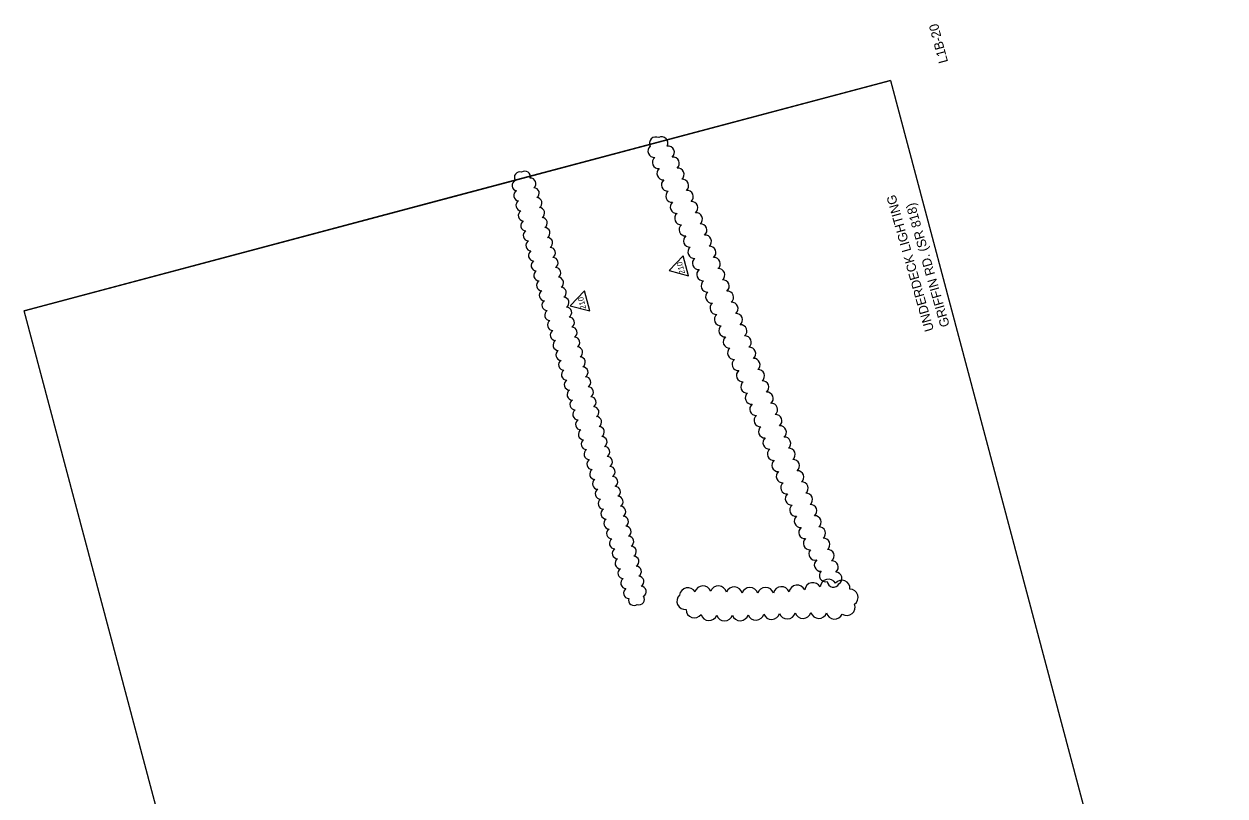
# Model space of a CAD drawing. Extents: x 930425 to 930963, y 629099 to 629760.
# Drawn here: x 930425 to 930939, y 629430 to 629760 of the extents above; entities that cross this region are included whole.
import ezdxf

# ---------------------------------------------------------------- set-up
doc = ezdxf.new("R2010")
doc.units = 0
for name, color, linetype in [('ActivePointCell_dp', 7, 'Continuous'), ('Cloud_dp', 7, 'Continuous'), ('MatchLines_dp', 7, 'Continuous'), ('TextShtNo', 7, 'Continuous'), ('TextTitle', 7, 'Continuous')]:
    doc.layers.add(name, color=color, linetype=linetype)

msp = doc.modelspace()

# ---------------------------------------------------------------- linework, layer by layer
at = {"layer": 'ActivePointCell_dp'}
msp.add_lwpolyline([(930567.78, 629098.98), (930424.61, 629637.39), (930795.69, 629736.06), (930938.85, 629197.65)], close=True, dxfattribs=at)
at = {"layer": 'Cloud_dp'}
for points in [[(930700.81, 629654.61), (930709.19, 629652.38), (930706.92, 629660.91)], [(930658.48, 629639.55), (930666.86, 629637.32), (930664.59, 629645.85)]]:
    msp.add_lwpolyline(points, close=True, dxfattribs=at)
for centre, radius, start, end in [((930695.16, 629709.11), 2.71, 63.2477, 208.2477), ((930697.65, 629709.14), 2.71, 332.9109, 117.9109), ((930694.48, 629705.73), 2.71, 128.986, 273.986), ((930700.39, 629705.22), 2.71, 312.0705, 97.0705), ((930696.39, 629700.94), 2.71, 129.4753, 274.4753), ((930702.48, 629700.51), 2.71, 310.9346, 95.9346), ((930704.51, 629695.77), 2.71, 310.3984, 95.3984), ((930636.89, 629694.51), 2.32, 70.1007, 215.1007), ((930639.1, 629694.86), 2.32, 342.9868, 127.9868), ((930641.48, 629691.87), 2.32, 309.1006, 94.1006), ((930698.31, 629696.14), 2.71, 129.2582, 274.2582), ((930700.22, 629691.34), 2.71, 129.1646, 274.1646), ((930706.5, 629691.02), 2.71, 310.0685, 95.0685), ((930635.93, 629691.06), 2.32, 113.8986, 258.8986), ((930636.61, 629686.76), 2.32, 119.116, 264.116), ((930642.9, 629687.76), 2.32, 303.8554, 88.8554), ((930702.13, 629686.54), 2.71, 129.1089, 274.1089), ((930708.48, 629686.25), 2.71, 309.8392, 94.8392), ((930637.55, 629682.46), 2.32, 120.4334, 265.4334), ((930644.08, 629683.52), 2.32, 302.3905, 87.3905), ((930704.03, 629681.74), 2.71, 129.0708, 274.0708), ((930710.43, 629681.47), 2.71, 309.6678, 94.6678), ((930638.56, 629678.17), 2.32, 121.1297, 266.1297), ((930645.22, 629679.25), 2.32, 302.3905, 87.3905), ((930705.92, 629676.94), 2.71, 129.0426, 274.0426), ((930712.37, 629676.69), 2.71, 309.5333, 94.5333), ((930639.62, 629673.88), 2.32, 121.5785, 266.5785), ((930646.35, 629674.98), 2.32, 302.3905, 87.3905), ((930647.5, 629670.71), 2.32, 302.5819, 87.5819), ((930707.82, 629672.13), 2.71, 129.0207, 274.0207), ((930714.3, 629671.9), 2.71, 309.4243, 94.4243), ((930640.7, 629669.6), 2.32, 121.8989, 266.8989), ((930648.65, 629666.44), 2.32, 302.7763, 87.7763), ((930709.71, 629667.33), 2.71, 129.003, 274.003), ((930716.23, 629667.11), 2.71, 309.3335, 94.3335), ((930641.81, 629665.33), 2.32, 122.1424, 267.1424), ((930642.93, 629661.06), 2.32, 122.3356, 267.3356), ((930649.82, 629662.18), 2.32, 302.7763, 87.7763), ((930711.61, 629662.52), 2.71, 128.9883, 273.9883), ((930718.15, 629662.32), 2.71, 309.2564, 94.2564), ((930644.07, 629656.79), 2.32, 122.4938, 267.4938), ((930650.98, 629657.92), 2.32, 302.7763, 87.7763), ((930713.5, 629657.72), 2.71, 128.9759, 273.9759), ((930720.06, 629657.52), 2.71, 309.1898, 94.1898), ((930645.22, 629652.53), 2.32, 122.6263, 267.6263), ((930652.15, 629653.66), 2.32, 302.7763, 87.7763), ((930715.39, 629652.91), 2.71, 128.9652, 273.9652), ((930721.96, 629652.72), 2.71, 309.1315, 94.1315), ((930646.37, 629648.27), 2.32, 122.7395, 267.7395), ((930653.31, 629649.4), 2.32, 302.7763, 87.7763), ((930654.47, 629645.13), 2.32, 302.7763, 87.7763), ((930717.28, 629648.11), 2.71, 128.9558, 273.9558), ((930723.86, 629647.92), 2.71, 309.08, 94.08), ((930647.54, 629644.01), 2.32, 122.8377, 267.8377), ((930655.64, 629640.87), 2.32, 302.7763, 87.7763), ((930719.16, 629643.3), 2.71, 128.9476, 273.9476), ((930725.76, 629643.12), 2.71, 309.0341, 94.0341), ((930648.71, 629639.75), 2.32, 122.9238, 267.9238), ((930649.89, 629635.49), 2.32, 123.0002, 268.0002), ((930656.8, 629636.61), 2.32, 302.7763, 87.7763), ((930721.05, 629638.49), 2.71, 128.9403, 273.9403), ((930727.65, 629638.32), 2.71, 308.9927, 93.9927), ((930651.07, 629631.23), 2.32, 123.0686, 268.0686), ((930657.97, 629632.35), 2.32, 302.7763, 87.7763), ((930722.94, 629633.69), 2.71, 128.9337, 273.9337), ((930729.54, 629633.51), 2.71, 308.9552, 93.9552), ((930652.26, 629626.98), 2.32, 123.1303, 268.1303), ((930659.13, 629628.09), 2.32, 302.7763, 87.7763), ((930724.83, 629628.88), 2.71, 128.9277, 273.9277), ((930731.43, 629628.71), 2.71, 308.921, 93.921), ((930733.31, 629623.9), 2.71, 308.8897, 93.8897), ((930653.45, 629622.73), 2.32, 123.1863, 268.1863), ((930660.29, 629623.82), 2.32, 302.7763, 87.7763), ((930661.46, 629619.56), 2.32, 302.7763, 87.7763), ((930726.71, 629624.07), 2.71, 128.9222, 273.9222), ((930728.6, 629619.27), 2.71, 128.9173, 273.9173), ((930735.2, 629619.09), 2.71, 308.8609, 93.8609), ((930654.65, 629618.47), 2.32, 123.2374, 268.2374), ((930662.62, 629615.3), 2.32, 302.7763, 87.7763), ((930730.48, 629614.46), 2.71, 128.9224, 273.9224), ((930737.08, 629614.28), 2.71, 308.8414, 93.8414), ((930655.85, 629614.22), 2.32, 123.2844, 268.2844), ((930657.05, 629609.97), 2.32, 123.3276, 268.3276), ((930663.79, 629611.04), 2.32, 302.7763, 87.7763), ((930732.37, 629609.65), 2.71, 128.9372, 273.9372), ((930738.96, 629609.47), 2.71, 308.8314, 93.8314), ((930658.26, 629605.72), 2.32, 123.3677, 268.3677), ((930664.95, 629606.78), 2.32, 302.7763, 87.7763), ((930734.26, 629604.85), 2.71, 128.9534, 273.9534), ((930740.83, 629604.66), 2.71, 308.8205, 93.8205), ((930659.47, 629601.47), 2.32, 123.3914, 268.3914), ((930666.11, 629602.52), 2.32, 302.7763, 87.7763), ((930736.15, 629600.04), 2.71, 128.9714, 273.9714), ((930742.71, 629599.85), 2.71, 308.8087, 93.8087), ((930660.68, 629597.22), 2.32, 123.3913, 268.3913), ((930667.28, 629598.25), 2.32, 302.7763, 87.7763), ((930668.44, 629593.99), 2.32, 302.7763, 87.7763), ((930738.04, 629595.24), 2.71, 128.9914, 273.9914), ((930744.59, 629595.04), 2.71, 308.7957, 93.7957), ((930661.89, 629592.97), 2.32, 123.3908, 268.3908), ((930663.1, 629588.72), 2.32, 123.3902, 268.3902), ((930669.61, 629589.73), 2.32, 302.7634, 87.7634), ((930739.93, 629590.43), 2.71, 129.0139, 274.0139), ((930746.46, 629590.23), 2.71, 308.7814, 93.7814), ((930664.3, 629584.48), 2.32, 123.3896, 268.3896), ((930670.77, 629585.47), 2.32, 302.738, 87.738), ((930741.83, 629585.63), 2.71, 129.0393, 274.0393), ((930748.33, 629585.42), 2.71, 308.7655, 93.7655), ((930665.51, 629580.23), 2.32, 123.3889, 268.3889), ((930671.93, 629581.2), 2.32, 302.7102, 87.7102), ((930743.72, 629580.83), 2.71, 129.0684, 274.0684), ((930750.21, 629580.61), 2.71, 308.7477, 93.7477), ((930666.72, 629575.98), 2.32, 123.3882, 268.3882), ((930673.09, 629576.94), 2.32, 302.6797, 87.6797), ((930745.62, 629576.03), 2.71, 129.1022, 274.1022), ((930752.08, 629575.79), 2.71, 308.7277, 93.7277), ((930667.93, 629571.73), 2.32, 123.3874, 268.3874), ((930674.24, 629572.68), 2.32, 302.646, 87.646), ((930675.39, 629568.41), 2.32, 302.6085, 87.6085), ((930747.52, 629571.23), 2.71, 129.1422, 274.1422), ((930753.95, 629570.98), 2.71, 308.7048, 93.7048), ((930669.14, 629567.48), 2.32, 123.3865, 268.3865), ((930670.35, 629563.23), 2.32, 123.3855, 268.3855), ((930676.54, 629564.15), 2.32, 302.5666, 87.5666), ((930749.43, 629566.43), 2.71, 129.1904, 274.1904), ((930755.81, 629566.17), 2.71, 308.6783, 93.6783), ((930671.56, 629558.98), 2.32, 123.3843, 268.3843), ((930677.69, 629559.88), 2.32, 302.519, 87.519), ((930751.34, 629561.63), 2.71, 129.2502, 274.2502), ((930757.68, 629561.35), 2.71, 308.6472, 93.6472), ((930672.77, 629554.73), 2.32, 123.3829, 268.3829), ((930678.83, 629555.61), 2.32, 302.4647, 87.4647), ((930753.26, 629556.84), 2.71, 129.327, 274.327), ((930759.54, 629556.53), 2.71, 308.6101, 93.6101), ((930673.98, 629550.48), 2.32, 123.3814, 268.3814), ((930679.97, 629551.35), 2.32, 302.4017, 87.4017), ((930681.1, 629547.08), 2.32, 302.3274, 87.3274), ((930755.18, 629552.05), 2.71, 129.4308, 274.4308), ((930757.12, 629547.26), 2.71, 129.5829, 274.5829), ((930761.39, 629551.72), 2.71, 308.5644, 93.5644), ((930763.25, 629546.9), 2.71, 308.5066, 93.5066), ((930675.19, 629546.23), 2.32, 123.3795, 268.3795), ((930682.23, 629542.81), 2.32, 302.238, 87.238), ((930759.07, 629542.49), 2.71, 129.8386, 274.8386), ((930765.09, 629542.08), 2.71, 308.4299, 93.4299), ((930676.4, 629541.98), 2.32, 123.3772, 268.3772), ((930677.61, 629537.73), 2.32, 123.3742, 268.3742), ((930683.35, 629538.53), 2.32, 302.1276, 87.1276), ((930761.05, 629537.73), 2.71, 130.4333, 275.4333), ((930766.93, 629537.25), 2.71, 308.321, 93.321), ((930678.81, 629533.48), 2.32, 123.3704, 268.3704), ((930684.46, 629534.26), 2.32, 301.9864, 86.9864), ((930763.37, 629533.28), 2.71, 139.5812, 284.5812), ((930768.76, 629532.43), 2.71, 308.1483, 93.1483), ((930680.02, 629529.23), 2.32, 123.3649, 268.3649), ((930685.56, 629529.98), 2.32, 301.7968, 86.7968), ((930765.72, 629528.53), 2.71, 128.2344, 273.2344), ((930770.57, 629527.59), 2.71, 307.8037, 92.8037), ((930681.23, 629524.98), 2.32, 123.3562, 268.3562), ((930686.64, 629525.7), 2.32, 301.5222, 86.5222), ((930687.69, 629521.42), 2.32, 301.0705, 86.0705), ((930767.89, 629524.02), 2.71, 137.9548, 282.9548), ((930772.11, 629522.75), 2.71, 302.6051, 87.6051), ((930682.44, 629520.73), 2.32, 123.3393, 268.3393), ((930688.69, 629517.12), 2.32, 300.0822, 85.0822), ((930708.85, 629515.25), 3.53, 29.4806, 174.4806), ((930715.32, 629516.05), 3.53, 19.6688, 164.6688), ((930721.95, 629516.01), 3.53, 14.6055, 159.6055), ((930728.63, 629515.59), 3.53, 13.1392, 158.1392), ((930735.43, 629515.33), 3.53, 17.4878, 162.4878), ((930742.17, 629515.39), 3.53, 18.5721, 163.5721), ((930748.94, 629515.68), 3.53, 21.3726, 166.3726), ((930755.7, 629516.36), 3.53, 24.9977, 169.9977), ((930762.4, 629517.43), 3.53, 28.1447, 173.1447), ((930769.03, 629518.86), 3.53, 31.3294, 176.3294), ((930771.18, 629521.72), 2.7, 187.3259, 332.3259), ((930774.75, 629518.44), 3.53, 355.1951, 140.1951), ((930683.64, 629516.48), 2.32, 123.3702, 268.3702), ((930685.78, 629513.45), 2.31, 162.046, 307.046), ((930687.96, 629513.78), 2.32, 250.2524, 35.2524), ((930707.69, 629512.97), 3.52, 131.8453, 276.8453), ((930778.23, 629514.62), 3.53, 304.4425, 89.4425), ((930711.63, 629509.41), 3.53, 179.1425, 324.1425), ((930776.94, 629510.43), 3.53, 236.2935, 21.2935), ((930717.91, 629508.24), 3.53, 194.655, 339.655), ((930724.57, 629508.08), 3.53, 197.6289, 342.6289), ((930731.27, 629508.18), 3.53, 199.0797, 344.0797), ((930737.98, 629508.42), 3.53, 199.9554, 344.9554), ((930744.7, 629508.71), 3.53, 199.9333, 344.9333), ((930751.43, 629508.96), 3.53, 199.4678, 344.4678), ((930758.16, 629509.15), 3.53, 198.6477, 343.6477), ((930764.93, 629509.15), 3.53, 196.4164, 341.4164), ((930771.71, 629508.82), 3.53, 192.9669, 337.9669)]:
    msp.add_arc(centre, radius, start, end, dxfattribs=at)
at = {"layer": 'MatchLines_dp'}
msp.add_lwpolyline([(930795.68, 629736.06), (930610.15, 629686.72), (930424.61, 629637.39)], dxfattribs=at)

# ---------------------------------------------------------------- texts
at = {"layer": 'Cloud_dp'}
for p in [(930707.67, 629653.4), (930665.34, 629638.34)]:
    msp.add_text('210', height=2.399, rotation=104.8905, dxfattribs=at).set_placement(p)
at = {"layer": 'TextShtNo'}
msp.add_text('L1B-20', height=4, rotation=104.8905, dxfattribs=at).set_placement((930820.31, 629743.97))
at = {"layer": 'TextTitle'}
for s, p in [('UNDERDECK LIGHTING', (930814.3, 629629.13)), ('GRIFFIN RD. (SR 818)', (930821.03, 629631.05))]:
    msp.add_text(s, height=4, rotation=105.9332, dxfattribs=at).set_placement(p)

doc.saveas('drawing.dxf')
